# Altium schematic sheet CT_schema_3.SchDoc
size 208 x 169 mm
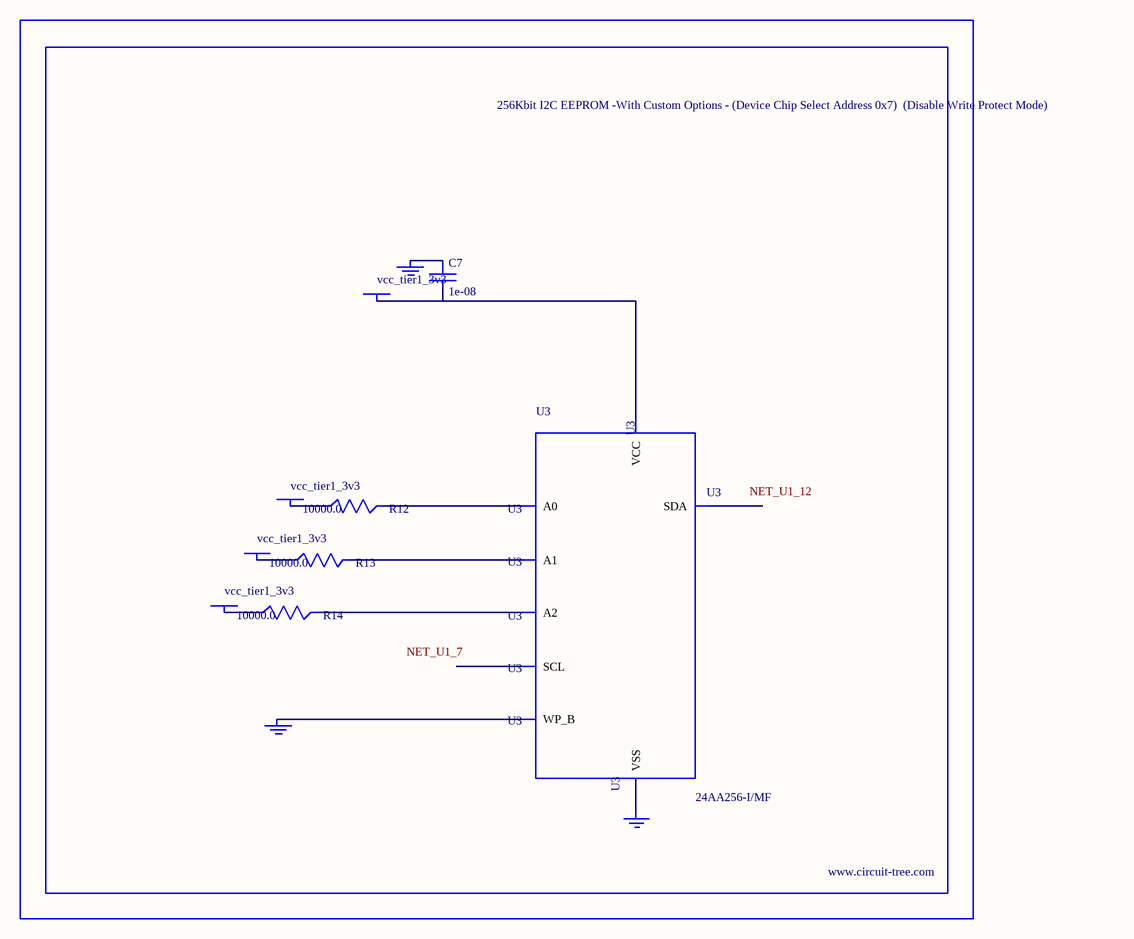
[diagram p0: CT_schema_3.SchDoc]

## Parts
BORDER2  (no value)
C7  1e-08  [C0402]
GND_INSTANCE_2_0  (no value)
GND_INSTANCE_2_1  (no value)
GND_INSTANCE_2_2  (no value)
POWER_INSTANCE_2_0  vcc_tier1_3v3
POWER_INSTANCE_2_1  vcc_tier1_3v3
POWER_INSTANCE_2_2  vcc_tier1_3v3
POWER_INSTANCE_2_3  vcc_tier1_3v3
R12  10000.0  [R0603]
R13  10000.0  [R0603]
R14  10000.0  [R0603]
U3  24AA256-I/MF  [DFN8-S]

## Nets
NetC7_1: C7.1 GND_INSTANCE_2_1.0(GND)
NetC7_2: C7.2 POWER_INSTANCE_2_3.0(PWR) U3.8(VCC)
NetGND_INSTANCE_2_0_0: GND_INSTANCE_2_0.0(GND) U3.7(WP_B)
NetGND_INSTANCE_2_2_0: GND_INSTANCE_2_2.0(GND) U3.4(VSS)
NetPOWER_INSTANCE_2_0_0: POWER_INSTANCE_2_0.0(PWR) R12.1
NetPOWER_INSTANCE_2_1_0: POWER_INSTANCE_2_1.0(PWR) R13.1
NetPOWER_INSTANCE_2_2_0: POWER_INSTANCE_2_2.0(PWR) R14.1
NetR12_2: R12.2 U3.1(A0)
NetR13_2: R13.2 U3.2(A1)
NetR14_2: R14.2 U3.3(A2)

Not connected (* = marked no-connect by the designer): U3 5(SDA) 6(SCL)

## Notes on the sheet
- Labels drawn without touching a wire or pin: NET_U1_7, NET_U1_12

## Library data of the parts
BORDER2 = BORDER_PAGE2
C7 = C0402C103K3RAC
GND_INSTANCE_2_0-GND_INSTANCE_2_2 = GND
POWER_INSTANCE_2_0-POWER_INSTANCE_2_3 = PWR
R12-R14 = RC0603JR-0710KL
